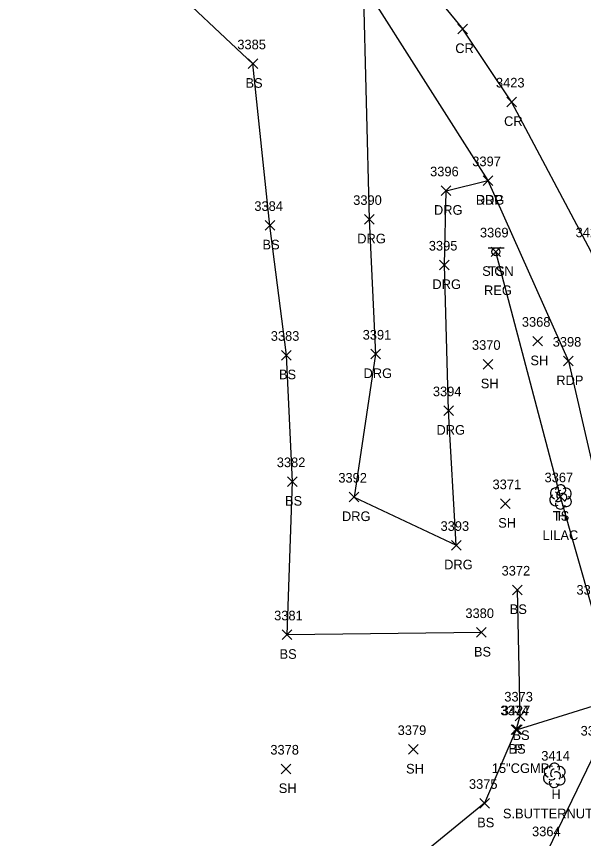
# Model space of a CAD drawing. Extents: x 1609623 to 1616187, y 756677 to 762826.
# Drawn here: x 1610470.6 to 1610588.6, y 762483.1 to 762654.1 of the extents above; entities that cross this region are included whole.
import ezdxf

# ---------------------------------------------------------------- set-up
doc = ezdxf.new("R2010")
doc.units = 0
for name, color, linetype in [('D_A', 7, 'Continuous'), ('D_C', 7, 'Continuous'), ('D_I', 7, 'Continuous'), ('D_TIC', 7, 'Continuous'), ('DCP', 7, 'Continuous'), ('L_A', 7, 'Continuous'), ('L_C', 7, 'Continuous'), ('L_I', 7, 'Continuous'), ('L_TIC', 7, 'Continuous'), ('LELB', 7, 'Continuous'), ('LTD', 7, 'Continuous'), ('P_A', 7, 'Continuous'), ('P_I', 7, 'Continuous'), ('P_TIC', 7, 'Continuous'), ('PET', 7, 'Continuous'), ('PRC', 7, 'Continuous'), ('R_A', 7, 'Continuous'), ('R_I', 7, 'Continuous'), ('R_TIC', 7, 'Continuous'), ('RDG', 7, 'Continuous'), ('S_A', 7, 'Continuous'), ('S_C', 7, 'Continuous'), ('S_I', 7, 'Continuous'), ('SSGN', 7, 'Continuous')]:
    doc.layers.add(name, color=color, linetype=linetype)

msp = doc.modelspace()

# ---------------------------------------------------------------- linework, layer by layer
at = {"layer": 'D_TIC'}
for points in [[(1610573.85, 762504.72), (1610575.85, 762506.72)], [(1610575.85, 762504.72), (1610573.85, 762506.72)]]:
    msp.add_lwpolyline(points, dxfattribs=at)
at = {"layer": 'DCP'}
msp.add_lwpolyline([(1610642.28, 762526.72), (1610574.85, 762505.72)], dxfattribs=at)
at = {"layer": 'L_TIC'}
for points in [[(1610518.86, 762643.23), (1610520.86, 762645.23)], [(1610520.86, 762643.23), (1610518.86, 762645.23)], [(1610522.4, 762609.62), (1610524.4, 762611.62)], [(1610524.4, 762609.62), (1610522.4, 762611.62)], [(1610569.39, 762604.11), (1610571.39, 762606.11)], [(1610571.39, 762604.11), (1610569.39, 762606.11)], [(1610578.1, 762585.53), (1610580.1, 762587.53)], [(1610580.1, 762585.53), (1610578.1, 762587.53)], [(1610525.82, 762582.61), (1610527.82, 762584.61)], [(1610527.82, 762582.61), (1610525.82, 762584.61)], [(1610567.76, 762580.73), (1610569.76, 762582.73)], [(1610569.76, 762580.73), (1610567.76, 762582.73)], [(1610527.07, 762556.33), (1610529.07, 762558.33)], [(1610529.07, 762556.33), (1610527.07, 762558.33)], [(1610582.83, 762553.19), (1610584.83, 762555.19)], [(1610584.83, 762553.19), (1610582.83, 762555.19)], [(1610571.39, 762551.75), (1610573.39, 762553.75)], [(1610573.39, 762551.75), (1610571.39, 762553.75)], [(1610573.84, 762533.79), (1610575.84, 762535.79)], [(1610575.84, 762533.79), (1610573.84, 762535.79)], [(1610566.39, 762524.95), (1610568.39, 762526.95)], [(1610568.39, 762524.95), (1610566.39, 762526.95)], [(1610525.95, 762524.47), (1610527.95, 762526.47)], [(1610527.95, 762524.47), (1610525.95, 762526.47)], [(1610574.41, 762507.59), (1610576.41, 762509.59)], [(1610576.41, 762507.59), (1610574.41, 762509.59)], [(1610573.59, 762504.74), (1610575.59, 762506.74)], [(1610575.59, 762504.74), (1610573.59, 762506.74)], [(1610552.22, 762500.62), (1610554.22, 762502.62)], [(1610554.22, 762500.62), (1610552.22, 762502.62)], [(1610525.73, 762496.56), (1610527.73, 762498.56)], [(1610527.73, 762496.56), (1610525.73, 762498.56)], [(1610567.05, 762489.43), (1610569.05, 762491.43)], [(1610569.05, 762489.43), (1610567.05, 762491.43)]]:
    msp.add_lwpolyline(points, dxfattribs=at)
at = {"layer": 'LELB'}
for points in [[(1610567.39, 762525.95), (1610526.95, 762525.47), (1610528.07, 762557.33), (1610526.82, 762583.61), (1610523.4, 762610.62), (1610519.86, 762644.23), (1610500.32, 762662.55), (1610470.64, 762692.89)], [(1610555.63, 762452.9), (1610570.89, 762459.22), (1610581.23, 762480.58), (1610591.33, 762501.51), (1610590.52, 762530.81), (1610583.83, 762554.19), (1610570.39, 762605.11)], [(1610574.84, 762534.79), (1610575.41, 762508.59), (1610574.59, 762505.74), (1610568.05, 762490.43), (1610545.56, 762472.08), (1610526.87, 762467.63)]]:
    msp.add_lwpolyline(points, dxfattribs=at)
at = {"layer": 'LTD'}
for p, q in [((1610583.83, 762554.19), (1610583.83, 762554.19)), ((1610583.83, 762554.19), (1610583.83, 762554.19)), ((1610582.53, 762496.3), (1610582.53, 762496.3)), ((1610582.53, 762496.3), (1610582.53, 762496.3))]:
    msp.add_line(p, q, dxfattribs=at)
for centre in [(1610583.88, 762555.62), (1610582.58, 762497.73)]:
    msp.add_arc(centre, 1.05, 335.5272, 180.9563, dxfattribs=at)
for centre, major_axis, ratio, start_param, end_param in [((1610583.04, 762554.86), (1.21, -0.51), 0.895232, 1.570796, 4.712389), ((1610584.87, 762554.77), (-1.14, -0.48), 0.949671, 1.570796, 4.712389), ((1610582.75, 762553.48), (0.58, -1.04), 0.959034, 3.141593, 6.283185), ((1610583.62, 762554.65), (-0.208, -0.792), 0.645439, 3.141593, 6.283185), ((1610584.33, 762554.02), (-0.5, 0.667), 0.989748, 3.141593, 6.283185), ((1610584.83, 762553.36), (-1.09, 0.79), 0.841452, 1.570796, 4.712389), ((1610583.83, 762552.69), (0.26, 1.06), 0.942809, 1.570796, 4.712389), ((1610583.37, 762553.44), (-0.625, -0.083), 0.423636, 0, 3.141593), ((1610581.74, 762496.96), (1.21, -0.51), 0.895232, 1.570796, 4.712389), ((1610582.32, 762496.76), (-0.208, -0.792), 0.645439, 3.141593, 6.283185), ((1610583.57, 762496.88), (-1.14, -0.48), 0.949671, 1.570796, 4.712389), ((1610581.45, 762495.59), (0.58, -1.04), 0.959034, 3.141593, 6.283185), ((1610583.03, 762496.13), (-0.5, 0.667), 0.989748, 3.141593, 6.283185), ((1610583.53, 762495.46), (-1.09, 0.79), 0.841452, 1.570796, 4.712389), ((1610582.53, 762494.8), (0.26, 1.06), 0.942809, 1.570796, 4.712389), ((1610582.07, 762495.55), (-0.625, -0.083), 0.423636, 0, 3.141593)]:
    msp.add_ellipse(centre, major_axis=major_axis, ratio=ratio, start_param=start_param, end_param=end_param, dxfattribs=at)
at = {"layer": 'P_TIC'}
for points in [[(1610562.51, 762650.45), (1610564.51, 762652.45)], [(1610564.51, 762650.45), (1610562.51, 762652.45)], [(1610572.67, 762635.29), (1610574.67, 762637.29)], [(1610574.67, 762635.29), (1610572.67, 762637.29)], [(1610567.73, 762618.92), (1610569.73, 762620.92)], [(1610569.73, 762618.92), (1610567.73, 762620.92)], [(1610584.48, 762581.39), (1610586.48, 762583.39)], [(1610586.48, 762581.39), (1610584.48, 762583.39)]]:
    msp.add_lwpolyline(points, dxfattribs=at)
at = {"layer": 'PET'}
msp.add_lwpolyline([(1610534.83, 762671.35), (1610542.81, 762660.78), (1610568.73, 762619.92), (1610585.48, 762582.39), (1610594.75, 762542.34), (1610600.31, 762494.84), (1610601.16, 762470.67)], dxfattribs=at)
at = {"layer": 'PRC'}
for points in [[(1610521.41, 762702.68), (1610563.51, 762651.45)], [(1610615.21, 762477.46), (1610610.95, 762522.65), (1610602.63, 762567.01), (1610590.24, 762605.14), (1610573.67, 762636.29), (1610563.51, 762651.45)]]:
    msp.add_lwpolyline(points, dxfattribs=at)
at = {"layer": 'R_TIC'}
for points in [[(1610567.73, 762618.92), (1610569.73, 762620.92)], [(1610569.73, 762618.92), (1610567.73, 762620.92)], [(1610559.02, 762616.82), (1610561.02, 762618.82)], [(1610561.02, 762616.82), (1610559.02, 762618.82)], [(1610543.06, 762610.87), (1610545.06, 762612.87)], [(1610545.06, 762610.87), (1610543.06, 762612.87)], [(1610558.7, 762601.38), (1610560.7, 762603.38)], [(1610560.7, 762601.38), (1610558.7, 762603.38)], [(1610544.37, 762582.86), (1610546.37, 762584.86)], [(1610546.37, 762582.86), (1610544.37, 762584.86)], [(1610559.55, 762571.08), (1610561.55, 762573.08)], [(1610561.55, 762571.08), (1610559.55, 762573.08)], [(1610539.88, 762553.12), (1610541.88, 762555.12)], [(1610541.88, 762553.12), (1610539.88, 762555.12)], [(1610561.14, 762543.08), (1610563.14, 762545.08)], [(1610563.14, 762543.08), (1610561.14, 762545.08)]]:
    msp.add_lwpolyline(points, dxfattribs=at)
at = {"layer": 'RDG'}
msp.add_lwpolyline([(1610542.81, 762660.78), (1610544.06, 762611.87), (1610545.37, 762583.86), (1610540.88, 762554.12), (1610562.14, 762544.08), (1610560.55, 762572.08), (1610559.7, 762602.38), (1610560.02, 762617.82), (1610568.73, 762619.92)], dxfattribs=at)
at = {"layer": 'SSGN'}
for p, q in [((1610568.76, 762605.97), (1610572.1, 762605.97)), ((1610570.41, 762605.13), (1610570.41, 762605.13))]:
    msp.add_line(p, q, dxfattribs=at)
msp.add_circle((1610570.41, 762605.13), 0.833, dxfattribs=at)

# ---------------------------------------------------------------- texts
at = {"layer": 'D_A'}
msp.add_text('P', height=2, dxfattribs=at).set_placement((1610574.23, 762500.72))
at = {"layer": 'D_C'}
msp.add_text('15"CGMP', height=2, dxfattribs=at).set_placement((1610569.55, 762496.72))
at = {"layer": 'D_I'}
msp.add_text('3427', height=2, dxfattribs=at).set_placement((1610571.59, 762508.72))
at = {"layer": 'L_A'}
for s, p in [('BS', (1610518.3, 762639.23)), ('BS', (1610521.84, 762605.62)), ('TS', (1610568.8, 762600.11)), ('SH', (1610577.59, 762581.53)), ('BS', (1610525.26, 762578.61)), ('SH', (1610567.25, 762576.73)), ('BS', (1610526.52, 762552.33)), ('TS', (1610582.24, 762549.19)), ('H', (1610583.26, 762549.19)), ('SH', (1610570.88, 762547.75)), ('BS', (1610573.28, 762529.79)), ('BS', (1610525.39, 762520.47)), ('BS', (1610565.83, 762520.95)), ('BS', (1610573.85, 762503.59)), ('BS', (1610573.03, 762500.74)), ('SH', (1610551.71, 762496.62)), ('SH', (1610525.22, 762492.56)), ('H', (1610581.96, 762491.3)), ('BS', (1610566.5, 762485.43))]:
    msp.add_text(s, height=2, dxfattribs=at).set_placement(p)
at = {"layer": 'L_C'}
for s, p in [('LILAC', (1610580.11, 762545.19)), ('S.BUTTERNUTT', (1610571.86, 762487.3))]:
    msp.add_text(s, height=2, dxfattribs=at).set_placement(p)
at = {"layer": 'L_I'}
for s, p in [('3385', (1610516.6, 762647.23)), ('3384', (1610520.14, 762613.62)), ('3369', (1610567.08, 762608.11)), ('3368', (1610575.8, 762589.53)), ('3383', (1610523.56, 762586.61)), ('3370', (1610565.42, 762584.73)), ('3382', (1610524.81, 762560.33)), ('3367', (1610580.52, 762557.19)), ('3367', (1610580.52, 762557.19)), ('3371', (1610569.7, 762555.75)), ('3372', (1610571.58, 762537.79)), ('3366', (1610587.16, 762533.81)), ('3381', (1610524.26, 762528.47)), ('3380', (1610564.05, 762528.95)), ('3373', (1610572.15, 762511.59)), ('3374', (1610571.33, 762508.74)), ('3379', (1610549.96, 762504.62)), ('3365', (1610588.02, 762504.51)), ('3378', (1610523.47, 762500.56)), ('3414', (1610579.84, 762499.3)), ('3375', (1610564.79, 762493.43)), ('3364', (1610577.92, 762483.58))]:
    msp.add_text(s, height=2, dxfattribs=at).set_placement(p)
at = {"layer": 'P_A'}
for s, p in [('CR', (1610561.94, 762646.45)), ('CR', (1610572.1, 762631.29)), ('RDP', (1610566.22, 762614.92)), ('RDP', (1610582.96, 762577.39))]:
    msp.add_text(s, height=2, dxfattribs=at).set_placement(p)
at = {"layer": 'P_I'}
for s, p in [('3423', (1610570.41, 762639.29)), ('3397', (1610565.48, 762622.92)), ('3422', (1610586.98, 762608.14)), ('3398', (1610582.22, 762585.39))]:
    msp.add_text(s, height=2, dxfattribs=at).set_placement(p)
at = {"layer": 'R_A'}
for p in [(1610566.22, 762614.92), (1610557.51, 762612.82), (1610541.55, 762606.87), (1610557.19, 762597.38), (1610542.86, 762578.86), (1610558.04, 762567.08), (1610538.37, 762549.12), (1610559.63, 762539.08)]:
    msp.add_text('DRG', height=2, dxfattribs=at).set_placement(p)
at = {"layer": 'R_I'}
for s, p in [('3397', (1610565.48, 762622.92)), ('3396', (1610556.71, 762620.82)), ('3390', (1610540.71, 762614.87)), ('3395', (1610556.44, 762605.38)), ('3391', (1610542.68, 762586.86)), ('3394', (1610557.29, 762575.08)), ('3392', (1610537.62, 762557.12)), ('3393', (1610558.88, 762547.08))]:
    msp.add_text(s, height=2, dxfattribs=at).set_placement(p)
at = {"layer": 'S_A'}
msp.add_text('SIGN', height=2, dxfattribs=at).set_placement((1610567.55, 762600.11))
at = {"layer": 'S_C'}
msp.add_text('REG', height=2, dxfattribs=at).set_placement((1610567.93, 762596.11))
at = {"layer": 'S_I'}
msp.add_text('3369', height=2, dxfattribs=at).set_placement((1610567.08, 762608.11))

doc.saveas('drawing.dxf')
